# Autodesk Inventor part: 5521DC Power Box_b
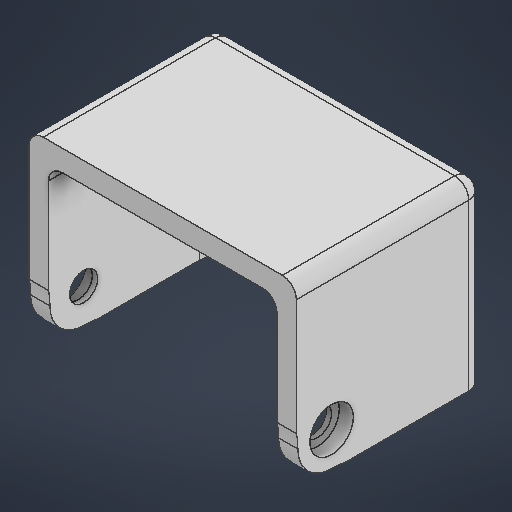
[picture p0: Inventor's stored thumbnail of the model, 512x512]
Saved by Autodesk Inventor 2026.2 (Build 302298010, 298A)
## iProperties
Created: 2026-05
Part Number: 5521DC Power Box_b
Material: 일반
Document SubType Name: Modeling
Designer: work
Density: 1 g/cm^3
Appearance: 기본값
Author: work
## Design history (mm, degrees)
sketch "스케치1"
  geometry: L1 (0, 0)-(22.5, 0); L2 (22.5, 0)-(22.5, -23.5); L3 (22.5, -23.5)-(0, -23.5); L4 (0, -23.5)-(0, 0); L5 (0, 0)-(25.5, 0); L6 (25.5, 0)-(25.5, -26.5); L7 (25.5, -26.5)-(0, -26.5); L8 (0, -26.5)-(0, 0); 3 further points
  constraints: 16 end point, 4 parallel, 2 horizontal, 2 perpendicular, 1 midpoint
  dimensions: "d0" = 22.5 distance of L2.end L3.end; "d1" = 23.5 distance of L1.end L2.end; "d2" = 3 distance from line of point (25.5, -13.25) L2; "d3" = 3 distance between parallel lines of L7 L3
extrude "돌출1" new body sketch "스케치1" stored distance "d4" = 38; taper "d5" = 0 deg
extrude "돌출2" cut sketch "스케치1" stored distance "d6" = 32.5; taper "d7" = 0 deg
sketch "스케치2"
  geometry: L1 (19, -25.5)-(19, -17.5); L2 (21.5, -25.5)-(21.5, -17.5); L3 (16.5, -17.5)-(16.5, -25.5); A1 r 2.5 centre (19, -25.5) between (16.5, -25.5) and (21.5, -25.5); A2 r 2.5 centre (19, -17.5) between (21.5, -17.5) and (16.5, -17.5); 1 further point
  constraints: 8 end point, 4 point on circle, 4 tangent, 2 centre point, 1 midpoint, 1 parallel, 1 vertical
  dimensions: "d8" = 2.5 radius of A2; "d9" = 8 distance of L1.start L1.end
extrude "돌출3" cut sketch "스케치2" distance "d10" = 31.5; taper "d11" = 0 deg
fillet "모깎기1" dims "d12" = 2
sketch "스케치3"
  geometry: C1 r 2 at (5, 5); 1 further point
  constraints: 1 centre point
  dimensions: "d13" = 4 diameter of C1; "d14" = 5 horizontal distance of point (0, 0) C1.centre; "d15" = 5 horizontal distance of point (0, 0) C1.centre
extrude "돌출4" cut sketch "스케치3" extent not by distance; stored distance "d16" = 0; taper "d17" = 0 deg
sketch "스케치4"
  geometry: C1 r 2 at (5, 5) reference; 2 further points
  constraints: 1 coincident
hole "구멍1" sketch "스케치4" at (5, 5) diameter "d18" = 4; stored, may be unused: countersink angle "d22" = 90 deg, drill point angle "d24" = 118 deg; dims "d19" = 6, "d20" = 6.2, "d21" = 2, "d23" = 8
sketch "스케치5"
  geometry: C1 r 2 at (-5, 5) reference; 2 further points
  constraints: 1 coincident
hole "구멍2" sketch "스케치5" at (-5, 5) diameter "d25" = 4; stored, may be unused: countersink angle "d29" = 90 deg, drill point angle "d31" = 118 deg; dims "d26" = 6, "d27" = 6.2, "d28" = 2, "d30" = 8
sketch "스케치6"
  geometry: L1 (24.5, 23.5)-(24.5, 0) reference; L2 (0, 23.5)-(24.5, 23.5) reference; L3 (0, 23.5)-(0, 0) reference; L4 (0, 0)-(24.5, 0) reference; C1 r 3.1 at (5, 5) reference; C2 r 5 at (5, 5); A1 r 4.8 centre (5, 5) between (5.005, 0.2) and (0.2, 5.005); A2 r 10 centre (5.015, -9.8) between (7.005, 0) and (5.005, 0.2); A3 r 10 centre (-9.8, 5.015) between (0.2, 5.005) and (0, 7.005); 1 further point
  constraints: 6 point on circle, 4 centre point, 3 tangent, 2 coincident, 2 point on line
  dimensions: "d32" = 0.2 radial gap between concentric circles of C2 A1; "d33" = 10 radius of A2; "d34" = 2 horizontal distance of A1.start A2.start; "d35" = 2 vertical distance of A1.end A3.end; "d36" = 10 radius of A3
extrude "돌출5" cut sketch "스케치6" extent not by distance; stored distance "d37" = 0; taper "d38" = 0 deg
node "솔리드1"
node "투영된 루프1"
feature "A9D066F2-1C7D-4E18-AEED-F7BC21143FA4" dims "d18" = 4, "d19" = 6, "d20" = 6.2, "d21" = 2, "d22" = 90 deg, "d23" = 8, "d24" = 118 deg
